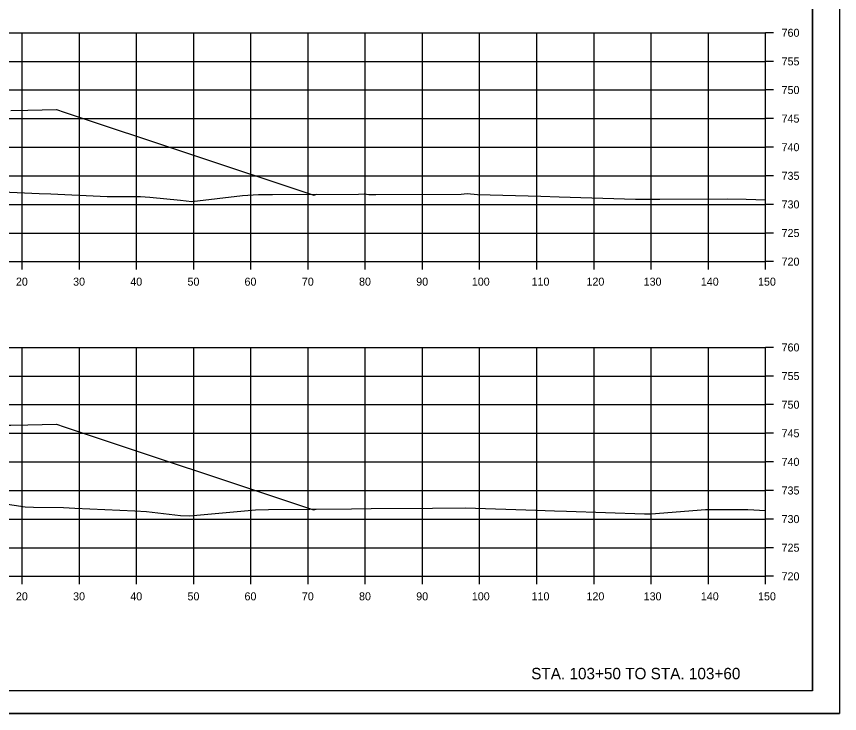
# Model space of a CAD drawing. Extents: x 1202951 to 1376887, y 378065 to 728038.
# Drawn here: x 1374304 to 1374447.9, y 379400 to 379521.8 of the extents above; entities that cross this region are included whole.
import ezdxf

# ---------------------------------------------------------------- set-up
doc = ezdxf.new("R2010")
doc.units = 0
for name, color, linetype in [('R_Axis', 7, 'Continuous'), ('R_Axis Annot', 7, 'Continuous'), ('R_Draft', 7, 'Continuous'), ('R_Exist Surface', 7, 'Continuous'), ('R_Fin Surface', 7, 'Continuous'), ('R_Grid', 7, 'Continuous'), ('R_No Plot', 7, 'Continuous')]:
    doc.layers.add(name, color=color, linetype=linetype)

msp = doc.modelspace()

# ---------------------------------------------------------------- linework, layer by layer
at = {"layer": 'R_Axis'}
for p, q in [((1374434.98, 379478.94), (1374434.98, 379518.94)), ((1374436.38, 379518.94), (1374434.98, 379518.94)), ((1374436.38, 379513.94), (1374434.98, 379513.94)), ((1374436.38, 379508.94), (1374434.98, 379508.94)), ((1374436.38, 379503.94), (1374434.98, 379503.94)), ((1374436.38, 379498.94), (1374434.98, 379498.94)), ((1374436.38, 379493.94), (1374434.98, 379493.94)), ((1374436.38, 379488.94), (1374434.98, 379488.94)), ((1374436.38, 379483.94), (1374434.98, 379483.94)), ((1374134.98, 379478.94), (1374434.98, 379478.94)), ((1374304.98, 379477.54), (1374304.98, 379478.94)), ((1374314.98, 379477.54), (1374314.98, 379478.94)), ((1374324.98, 379477.54), (1374324.98, 379478.94)), ((1374334.98, 379477.54), (1374334.98, 379478.94)), ((1374344.98, 379477.54), (1374344.98, 379478.94)), ((1374354.98, 379477.54), (1374354.98, 379478.94)), ((1374364.98, 379477.54), (1374364.98, 379478.94)), ((1374374.98, 379477.54), (1374374.98, 379478.94)), ((1374384.98, 379477.54), (1374384.98, 379478.94)), ((1374394.98, 379477.54), (1374394.98, 379478.94)), ((1374404.98, 379477.54), (1374404.98, 379478.94)), ((1374414.98, 379477.54), (1374414.98, 379478.94)), ((1374424.98, 379477.54), (1374424.98, 379478.94)), ((1374434.98, 379477.54), (1374434.98, 379478.94)), ((1374436.38, 379478.94), (1374434.98, 379478.94)), ((1374434.98, 379423.94), (1374434.98, 379463.94)), ((1374436.38, 379463.94), (1374434.98, 379463.94)), ((1374436.38, 379458.94), (1374434.98, 379458.94)), ((1374436.38, 379453.94), (1374434.98, 379453.94)), ((1374436.38, 379448.94), (1374434.98, 379448.94)), ((1374436.38, 379443.94), (1374434.98, 379443.94)), ((1374436.38, 379438.94), (1374434.98, 379438.94)), ((1374436.38, 379433.94), (1374434.98, 379433.94)), ((1374436.38, 379428.94), (1374434.98, 379428.94)), ((1374134.98, 379423.94), (1374434.98, 379423.94)), ((1374304.98, 379422.54), (1374304.98, 379423.94)), ((1374314.98, 379422.54), (1374314.98, 379423.94)), ((1374324.98, 379422.54), (1374324.98, 379423.94)), ((1374334.98, 379422.54), (1374334.98, 379423.94)), ((1374344.98, 379422.54), (1374344.98, 379423.94)), ((1374354.98, 379422.54), (1374354.98, 379423.94)), ((1374364.98, 379422.54), (1374364.98, 379423.94)), ((1374374.98, 379422.54), (1374374.98, 379423.94)), ((1374384.98, 379422.54), (1374384.98, 379423.94)), ((1374394.98, 379422.54), (1374394.98, 379423.94)), ((1374404.98, 379422.54), (1374404.98, 379423.94)), ((1374414.98, 379422.54), (1374414.98, 379423.94)), ((1374424.98, 379422.54), (1374424.98, 379423.94)), ((1374434.98, 379422.54), (1374434.98, 379423.94)), ((1374436.38, 379423.94), (1374434.98, 379423.94))]:
    msp.add_line(p, q, dxfattribs=at)
at = {"layer": 'R_Exist Surface'}
for points in [[(1374301.55, 379491.15), (1374307.94, 379490.82), (1374310, 379490.8), (1374319.84, 379490.32), (1374324.66, 379490.35), (1374325.7, 379490.33), (1374327.31, 379490.23), (1374332.68, 379489.7), (1374334.64, 379489.47), (1374343.49, 379490.47), (1374346.32, 379490.68), (1374347.87, 379490.68), (1374348.61, 379490.67), (1374348.74, 379490.68), (1374363.78, 379490.75), (1374364.77, 379490.77), (1374365.61, 379490.7), (1374366.81, 379490.66), (1374381.76, 379490.76), (1374382.79, 379490.82), (1374384.63, 379490.69), (1374395.68, 379490.36), (1374398.89, 379490.24), (1374412.25, 379489.85), (1374412.99, 379489.84), (1374416.51, 379489.86), (1374428.38, 379489.9), (1374431.61, 379489.88), (1374434.98, 379489.77)], [(1374301.64, 379436.69), (1374305.52, 379436.1), (1374306.98, 379436.03), (1374312.21, 379435.97), (1374314.19, 379435.87), (1374324.7, 379435.39), (1374326.73, 379435.29), (1374332.65, 379434.57), (1374334.22, 379434.48), (1374345.78, 379435.55), (1374348.06, 379435.61), (1374362.55, 379435.74), (1374366.02, 379435.77), (1374376.76, 379435.87), (1374382.5, 379435.89), (1374394.82, 379435.48), (1374398.04, 379435.39), (1374400.17, 379435.32), (1374413.79, 379434.85), (1374414.07, 379434.85), (1374414.96, 379434.85), (1374424.47, 379435.59), (1374431.9, 379435.62), (1374434.98, 379435.47)]]:
    msp.add_lwpolyline(points, dxfattribs=at)
at = {"layer": 'R_Fin Surface'}
for points in [[(1374302.98, 379505.37), (1374305.98, 379505.43), (1374310.98, 379505.53), (1374312.32, 379505.09), (1374355.96, 379490.54), (1374356.49, 379490.71)], [(1374174.32, 379440.29), (1374181.37, 379437.94), (1374184.98, 379436.74), (1374188.7, 379436.74), (1374218.69, 379446.74), (1374220.98, 379448.74), (1374221.98, 379448.74), (1374247.98, 379450.3), (1374252.98, 379450.2), (1374255.98, 379450.14), (1374256.47, 379450.14), (1374256.48, 379449.64), (1374257.48, 379449.66), (1374284.98, 379450.21), (1374301.48, 379449.88), (1374302.48, 379449.86), (1374302.49, 379450.36), (1374302.98, 379450.36), (1374305.98, 379450.42), (1374310.98, 379450.52), (1374312.32, 379450.07), (1374355.92, 379435.54), (1374356.37, 379435.69)]]:
    msp.add_lwpolyline(points, dxfattribs=at)
at = {"layer": 'R_Grid'}
for p, q in [((1374134.98, 379518.94), (1374434.98, 379518.94)), ((1374304.98, 379478.94), (1374304.98, 379518.94)), ((1374314.98, 379478.94), (1374314.98, 379518.94)), ((1374324.98, 379478.94), (1374324.98, 379518.94)), ((1374334.98, 379478.94), (1374334.98, 379518.94)), ((1374344.98, 379478.94), (1374344.98, 379518.94)), ((1374354.98, 379478.94), (1374354.98, 379518.94)), ((1374364.98, 379478.94), (1374364.98, 379518.94)), ((1374374.98, 379478.94), (1374374.98, 379518.94)), ((1374384.98, 379478.94), (1374384.98, 379518.94)), ((1374394.98, 379478.94), (1374394.98, 379518.94)), ((1374404.98, 379478.94), (1374404.98, 379518.94)), ((1374414.98, 379478.94), (1374414.98, 379518.94)), ((1374424.98, 379478.94), (1374424.98, 379518.94)), ((1374434.98, 379478.94), (1374434.98, 379518.94)), ((1374134.98, 379513.94), (1374434.98, 379513.94)), ((1374134.98, 379508.94), (1374434.98, 379508.94)), ((1374134.98, 379503.94), (1374434.98, 379503.94)), ((1374134.98, 379498.94), (1374434.98, 379498.94)), ((1374134.98, 379493.94), (1374434.98, 379493.94)), ((1374134.98, 379488.94), (1374434.98, 379488.94)), ((1374134.98, 379483.94), (1374434.98, 379483.94)), ((1374134.98, 379478.94), (1374434.98, 379478.94)), ((1374134.98, 379463.94), (1374434.98, 379463.94)), ((1374304.98, 379423.94), (1374304.98, 379463.94)), ((1374314.98, 379423.94), (1374314.98, 379463.94)), ((1374324.98, 379423.94), (1374324.98, 379463.94)), ((1374334.98, 379423.94), (1374334.98, 379463.94)), ((1374344.98, 379423.94), (1374344.98, 379463.94)), ((1374354.98, 379423.94), (1374354.98, 379463.94)), ((1374364.98, 379423.94), (1374364.98, 379463.94)), ((1374374.98, 379423.94), (1374374.98, 379463.94)), ((1374384.98, 379423.94), (1374384.98, 379463.94)), ((1374394.98, 379423.94), (1374394.98, 379463.94)), ((1374404.98, 379423.94), (1374404.98, 379463.94)), ((1374414.98, 379423.94), (1374414.98, 379463.94)), ((1374424.98, 379423.94), (1374424.98, 379463.94)), ((1374434.98, 379423.94), (1374434.98, 379463.94)), ((1374134.98, 379458.94), (1374434.98, 379458.94)), ((1374134.98, 379453.94), (1374434.98, 379453.94)), ((1374134.98, 379448.94), (1374434.98, 379448.94)), ((1374134.98, 379443.94), (1374434.98, 379443.94)), ((1374134.98, 379438.94), (1374434.98, 379438.94)), ((1374134.98, 379433.94), (1374434.98, 379433.94)), ((1374134.98, 379428.94), (1374434.98, 379428.94)), ((1374134.98, 379423.94), (1374434.98, 379423.94))]:
    msp.add_line(p, q, dxfattribs=at)
at = {"layer": 'R_No Plot'}
for p, q in [((1374443.16, 379403.94), (1374443.16, 379609.4)), ((1374443.16, 379403.94), (1374126.98, 379403.94)), ((1374114.58, 379399.96), (1374447.91, 379399.96))]:
    msp.add_line(p, q, dxfattribs=at)
for points in [[(1374114.57, 379613.29), (1374447.91, 379613.29), (1374447.91, 379399.95), (1374114.57, 379399.95)], [(1374360.9, 379609.4), (1374380.52, 379609.4), (1374380.52, 379599.52), (1374396.63, 379599.52), (1374419.83, 379599.52), (1374419.83, 379575.18), (1374443.16, 379575.18), (1374443.16, 379403.94), (1374126.98, 379403.94), (1374126.98, 379609.4)]]:
    msp.add_lwpolyline(points, close=True, dxfattribs=at)

# ---------------------------------------------------------------- texts
at = {"layer": 'R_Axis Annot'}
for s, p in [('760', (1374437.78, 379518.24)), ('755', (1374437.78, 379513.24)), ('750', (1374437.78, 379508.24)), ('745', (1374437.78, 379503.24)), ('740', (1374437.78, 379498.24)), ('735', (1374437.78, 379493.24)), ('730', (1374437.78, 379488.24)), ('725', (1374437.78, 379483.24)), ('720', (1374437.78, 379478.24)), ('20', (1374303.89, 379474.74)), ('30', (1374313.89, 379474.74)), ('40', (1374323.89, 379474.74)), ('50', (1374333.89, 379474.74)), ('60', (1374343.86, 379474.74)), ('70', (1374353.89, 379474.74)), ('80', (1374363.89, 379474.74)), ('90', (1374373.89, 379474.74)), ('100', (1374383.61, 379474.74)), ('110', (1374394.06, 379474.74)), ('120', (1374403.66, 379474.74)), ('130', (1374413.66, 379474.74)), ('140', (1374423.66, 379474.74)), ('150', (1374433.66, 379474.74)), ('760', (1374437.78, 379463.24)), ('755', (1374437.78, 379458.24)), ('750', (1374437.78, 379453.24)), ('745', (1374437.78, 379448.24)), ('740', (1374437.78, 379443.24)), ('735', (1374437.78, 379438.24)), ('730', (1374437.78, 379433.24)), ('725', (1374437.78, 379428.24)), ('720', (1374437.78, 379423.24)), ('20', (1374303.89, 379419.74)), ('30', (1374313.89, 379419.74)), ('40', (1374323.89, 379419.74)), ('50', (1374333.89, 379419.74)), ('60', (1374343.86, 379419.74)), ('70', (1374353.89, 379419.74)), ('80', (1374363.89, 379419.74)), ('90', (1374373.89, 379419.74)), ('100', (1374383.61, 379419.74)), ('110', (1374394.06, 379419.74)), ('120', (1374403.66, 379419.74)), ('130', (1374413.66, 379419.74)), ('140', (1374423.66, 379419.74)), ('150', (1374433.66, 379419.74))]:
    msp.add_text(s, height=1.4, dxfattribs=at).set_placement(p)
at = {"layer": 'R_Draft'}
msp.add_text('STA. 103+50 TO STA. 103+60', height=2, dxfattribs=at).set_placement((1374394, 379405.94))

doc.saveas('drawing.dxf')
